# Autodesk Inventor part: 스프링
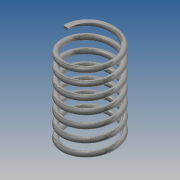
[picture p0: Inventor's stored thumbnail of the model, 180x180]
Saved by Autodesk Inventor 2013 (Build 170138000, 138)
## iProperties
Created: 2014-12
Part Number: 스프링
Material: 강철, 탄소
Document SubType Name: Modeling
Designer: CAD-B22
Density: 7.87 g/cm^3
Mass: 161.108 g
Surface Area: 165.536 cm^2
Volume: 20.4712 cm^3
Author: CAD-B22
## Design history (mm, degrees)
sketch "스케치1"
  geometry: L1 (0, 0)-(-24, 0); L2 (-24, 0)-(-24, 84.25); L3 (-24, 84.25)-(0, 84.25); L4 (0, 84.25)-(0, 0); C1 r 2.5 at (0, 0)
  constraints: 8 end point, 2 parallel, 1 centre point, 1 coincident, 1 horizontal, 1 perpendicular
  dimensions: "d0" = 84.25 distance of L3.end L1.start (derived); "d1" = 5 diameter of C1; "d2" = 48 diameter of L4 L2
feature "코일1" pitch "d3" = 10; turns "d5" = 7; dims "d4" = 84.25 (= d0), "d6" = 0, angle "d7" = 90 deg, angle "d8" = 90 deg, "d9" = 0, "d10" = 0
sketch "스케치2"
  geometry: L1 (-2.5, 0)-(2.5, 0) reference; L2 (-2.5, 0)-(2.5, 0) reference; L3 (-2.5, 0)-(2.5, 0) reference; 1 further point
  constraints: 3 horizontal alignment
extrude "돌출1" cut sketch "스케치2" distance "d11" = 10; taper "d12" = 0 deg
node "작업 평면1"
sketch "스케치3"
  geometry: L1 (2.5, 0)-(-2.5, 0) reference; 1 further point
  constraints: 1 horizontal alignment
extrude "돌출2" cut sketch "스케치3" distance "d13" = 10; taper "d14" = 0 deg
node "솔리드1"
node "절단 모서리 투영1"
node "절단 모서리 투영2"
node "절단 모서리 투영3"
node "절단 모서리 투영4"
